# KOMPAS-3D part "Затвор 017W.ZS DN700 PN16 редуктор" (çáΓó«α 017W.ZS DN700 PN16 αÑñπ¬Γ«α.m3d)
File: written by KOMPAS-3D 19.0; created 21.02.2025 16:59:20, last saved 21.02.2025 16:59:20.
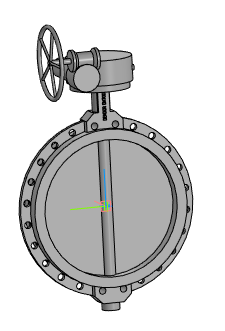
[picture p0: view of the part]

Document properties: Автор: Евгений; Полное имя файла: Затвор 017W.ZS DN700 PN16 редуктор.a3d

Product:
- Part/product: Затвор 017W.ZS DN700 PN16 редуктор
    Масса: 444.117

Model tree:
1. Операция без истории:1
